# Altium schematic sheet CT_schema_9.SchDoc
size 391 x 238 mm
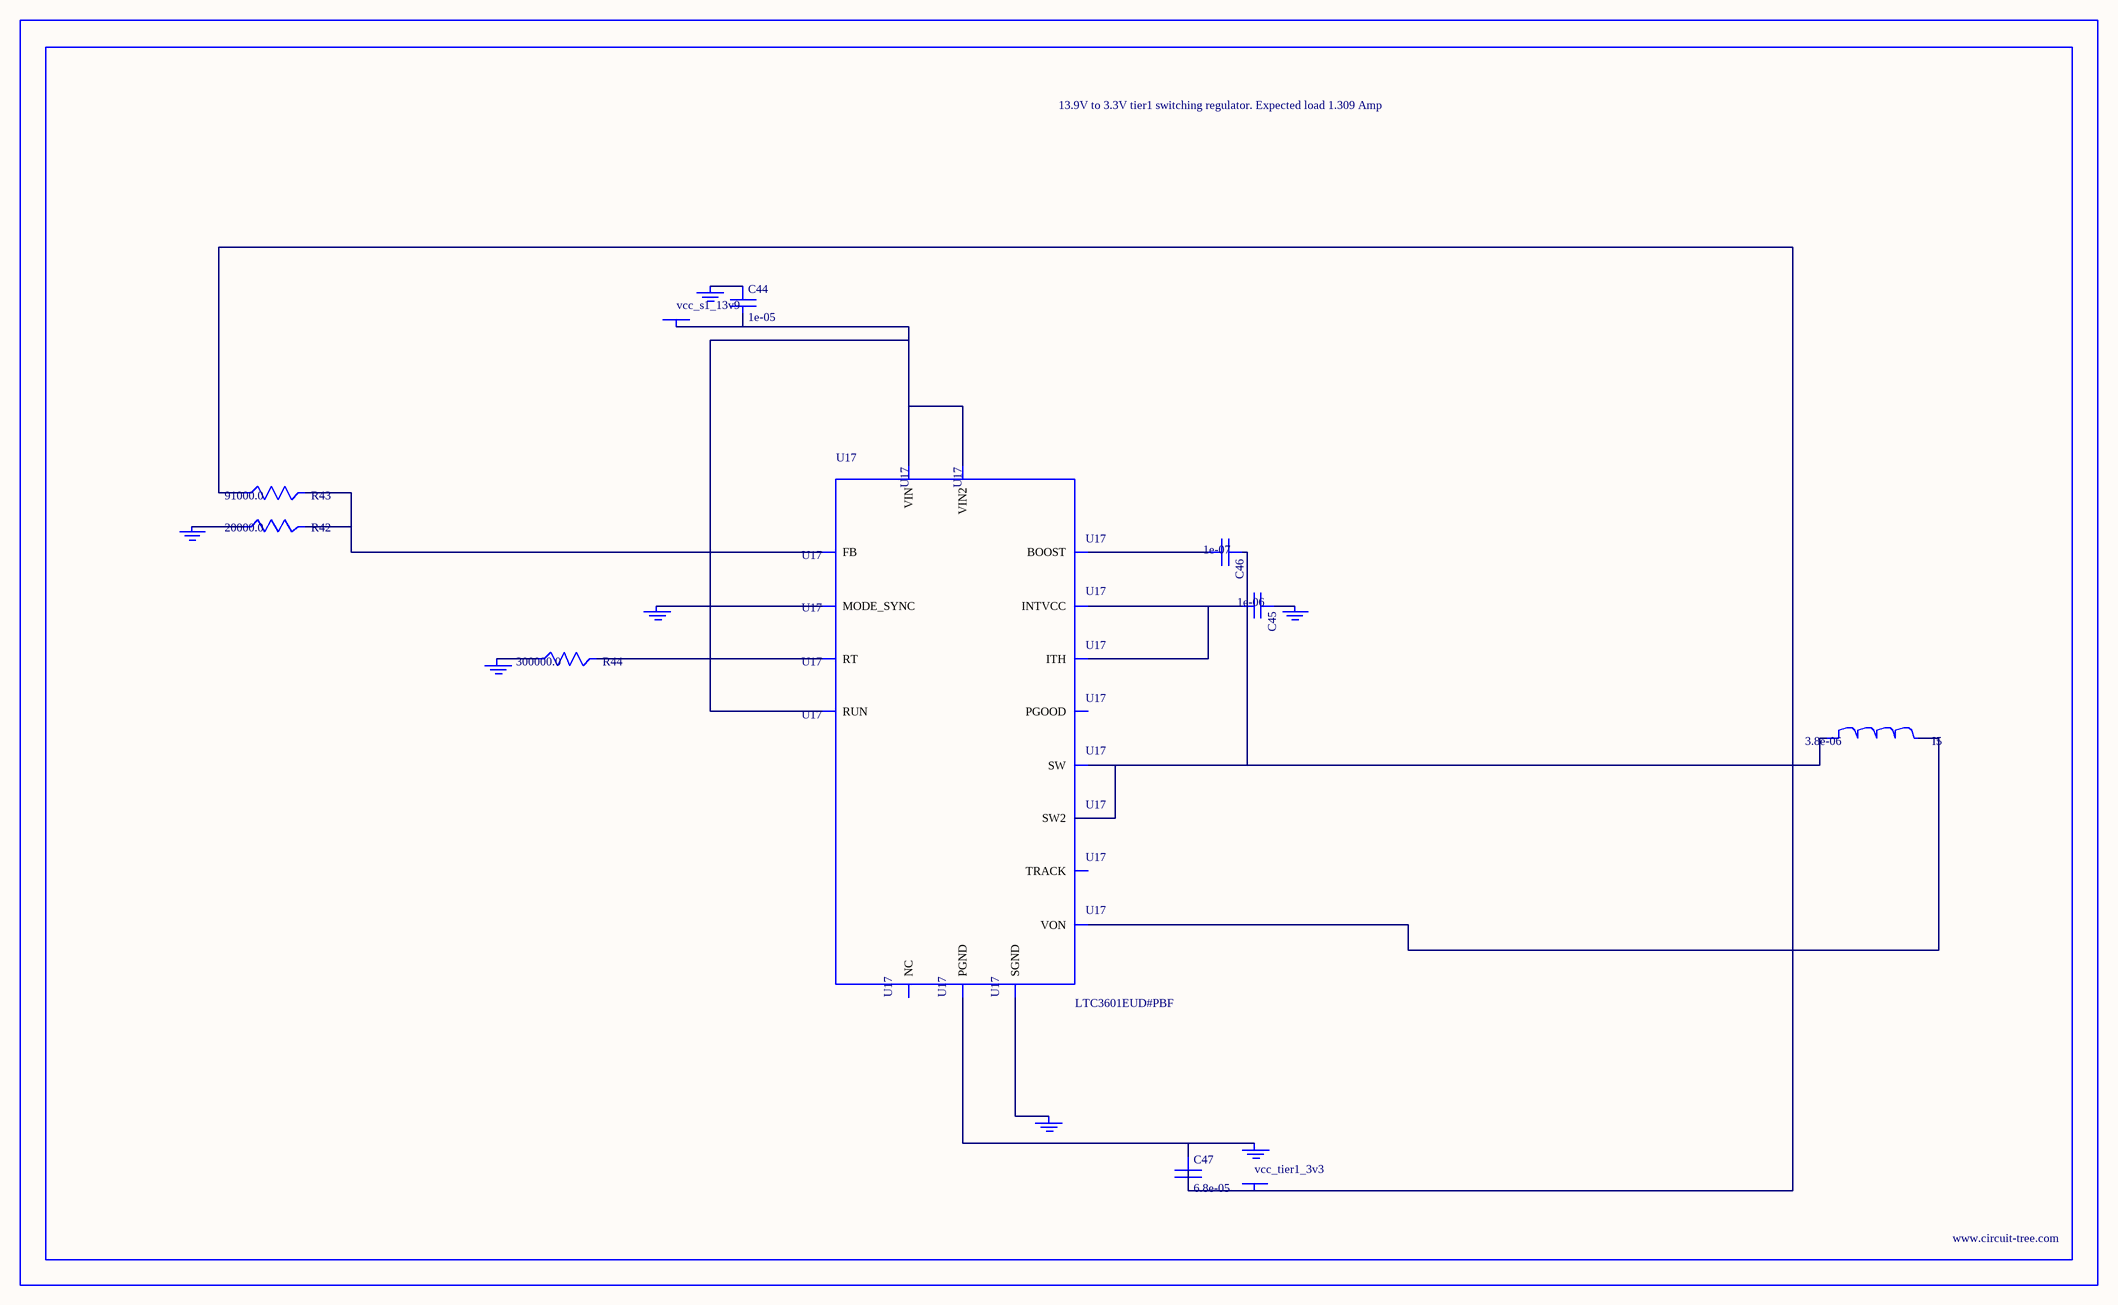
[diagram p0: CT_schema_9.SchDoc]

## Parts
BORDER8  (no value)
C44  1e-05  [C0805]
C45  1e-06  [C0603]
C46  1e-07  [C0402]
C47  6.8e-05  [2220]
GND_INSTANCE_8_0  (no value)
GND_INSTANCE_8_1  (no value)
GND_INSTANCE_8_2  (no value)
GND_INSTANCE_8_3  (no value)
GND_INSTANCE_8_4  (no value)
GND_INSTANCE_8_5  (no value)
GND_INSTANCE_8_6  (no value)
I5  3.8e-06  [DR1040]
POWER_INSTANCE_8_0  vcc_s1_13v9
POWER_INSTANCE_8_1  vcc_tier1_3v3
R42  20000.0  [R0603]
R43  91000.0  [R0603]
R44  300000.0  [R0603]
U17  LTC3601EUD#PBF  [QFN-16_EP]

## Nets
NetC44_1: C44.1 GND_INSTANCE_8_5.0(GND)
NetC44_2: C44.2 POWER_INSTANCE_8_0.0(PWR) U17.14(RUN) U17.15(VIN) U17.16(VIN2)
NetC45_1: C45.1 GND_INSTANCE_8_1.0(GND)
NetC45_2: C45.2 U17.7(INTVCC) U17.12(ITH)
NetC46_1: C46.1 I5.1 U17.3(SW) U17.4(SW2)
NetC46_2: C46.2 U17.6(BOOST)
NetC47_1: C47.1 GND_INSTANCE_8_6.0(GND) U17.17(PGND)
NetC47_2: C47.2 I5.2 POWER_INSTANCE_8_1.0(PWR) R43.1 U17.8(VON)
NetGND_INSTANCE_8_0_0: GND_INSTANCE_8_0.0(GND) U17.1(MODE_SYNC)
NetGND_INSTANCE_8_2_0: GND_INSTANCE_8_2.0(GND) U17.9(SGND)
NetGND_INSTANCE_8_3_0: GND_INSTANCE_8_3.0(GND) R44.1
NetGND_INSTANCE_8_4_0: GND_INSTANCE_8_4.0(GND) R42.1
NetR42_2: R42.2 R43.2 U17.11(FB)
NetR44_2: R44.2 U17.10(RT)

Not connected (* = marked no-connect by the designer): U17 2(PGOOD) 5(NC) 13(TRACK)

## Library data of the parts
BORDER8 = BORDER_PAGE8
C44 = C0805C106K8RACTU
C45 = C0603C105K3RACTU
C46 = C0402C104K3RACTU
C47 = C5750X5R1A686M
GND_INSTANCE_8_0-GND_INSTANCE_8_6 = GND
I5 = DR1040-3R8-R
POWER_INSTANCE_8_0 POWER_INSTANCE_8_1 = PWR
R42 = RC0603JR-0720KL
R43 = RC0603JR-0791KL
R44 = RC0603JR-07300KL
